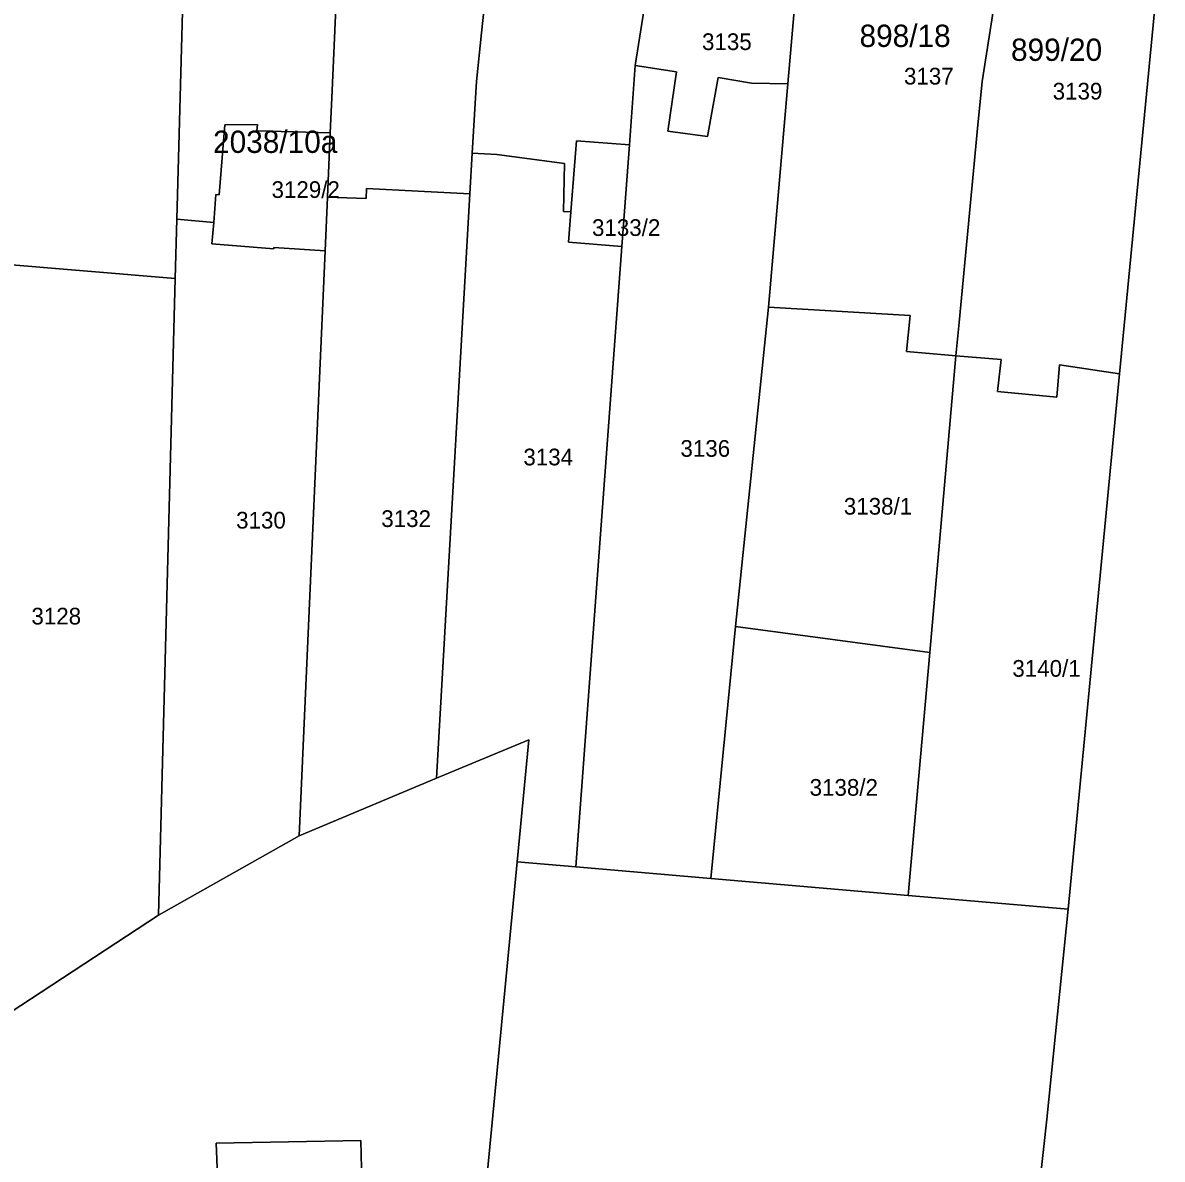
# Model space of a CAD drawing. Extents: x -570104 to -569328, y -1087857 to -1087418.
# Drawn here: x -569987.5 to -569885.2, y -1087663.8 to -1087561.8 of the extents above; entities that cross this region are included whole.
import ezdxf

# ---------------------------------------------------------------- set-up
doc = ezdxf.new("R2010")
doc.units = 0
for name, color, linetype in [('Adresní místo-text', 7, 'Continuous'), ('Parcela-polygon', 7, 'Continuous'), ('Parcela-text', 7, 'Continuous')]:
    doc.layers.add(name, color=color, linetype=linetype)

msp = doc.modelspace()

# ---------------------------------------------------------------- linework, layer by layer
at = {"layer": 'Parcela-polygon'}
for points in [[(-569997.88, -1087582.73), (-569973.85, -1087584.72), (-569973.7, -1087579.41), (-569973.18, -1087559.65), (-569972.91, -1087549.54), (-569973.1, -1087545.91), (-569997.57, -1087542.16), (-569997.86, -1087579.86)], [(-569959.94, -1087571.66), (-569959.81, -1087568.52), (-569958.91, -1087548.36), (-569973.1, -1087545.91), (-569972.91, -1087549.54), (-569973.18, -1087559.65), (-569973.7, -1087579.41), (-569970.4, -1087579.69), (-569970.2, -1087577.18), (-569969.9, -1087577.21), (-569969.4, -1087570.94), (-569966.47, -1087570.91), (-569966.53, -1087571.47)], [(-569947.4, -1087577.14), (-569947.19, -1087573.49), (-569946.82, -1087567.06), (-569946.35, -1087562.68), (-569945.39, -1087553.75), (-569944.82, -1087550.4), (-569958.91, -1087548.36), (-569959.81, -1087568.52), (-569959.94, -1087571.66), (-569960.2, -1087577.43), (-569956.73, -1087577.55), (-569956.69, -1087576.64)], [(-569932.55, -1087565.62), (-569931.05, -1087555.99), (-569930.47, -1087552.71), (-569944.82, -1087550.4), (-569945.39, -1087553.75), (-569946.35, -1087562.68), (-569946.82, -1087567.06), (-569947.19, -1087573.49), (-569944.97, -1087573.6), (-569938.9, -1087574.4), (-569939.01, -1087578.73), (-569938.34, -1087578.75), (-569937.83, -1087572.37), (-569933.08, -1087572.73)], [(-569918.85, -1087567.26), (-569917.76, -1087554.5), (-569930.47, -1087552.71), (-569931.05, -1087555.99), (-569932.55, -1087565.62), (-569928.85, -1087566.18), (-569929.63, -1087571.5), (-569926.07, -1087571.99), (-569925.11, -1087566.7), (-569922.12, -1087567.19)], [(-569899.84, -1087557.01), (-569917.76, -1087554.5), (-569918.85, -1087567.26), (-569920.58, -1087587.3), (-569907.88, -1087588.06), (-569908.19, -1087591.28), (-569904.44, -1087591.6), (-569903.76, -1087591.66), (-569903.47, -1087588.67), (-569902.54, -1087578.87), (-569901.97, -1087572.86), (-569901.85, -1087571.57), (-569901.42, -1087567.06), (-569900.4, -1087560.56)], [(-569889.08, -1087593.3), (-569885.83, -1087559.47), (-569899.84, -1087557.01), (-569900.4, -1087560.56), (-569901.42, -1087567.06), (-569901.85, -1087571.57), (-569901.97, -1087572.86), (-569902.54, -1087578.87), (-569903.47, -1087588.67), (-569903.76, -1087591.66), (-569899.7, -1087591.99), (-569900.03, -1087594.86), (-569894.72, -1087595.39), (-569894.48, -1087592.49)], [(-569933.08, -1087572.73), (-569933.75, -1087581.85), (-569937.9, -1087637.54), (-569925.77, -1087638.58), (-569923.57, -1087615.97), (-569920.58, -1087587.3), (-569918.85, -1087567.26), (-569922.12, -1087567.19), (-569925.11, -1087566.7), (-569926.07, -1087571.99), (-569929.63, -1087571.5), (-569928.85, -1087566.18), (-569932.55, -1087565.62)], [(-569959.94, -1087571.66), (-569966.53, -1087571.47), (-569966.47, -1087570.91), (-569969.4, -1087570.94), (-569969.9, -1087577.21), (-569970.2, -1087577.18), (-569970.4, -1087579.69), (-569970.56, -1087581.62), (-569965.01, -1087582.06), (-569965.01, -1087581.96), (-569960.41, -1087582.26), (-569960.2, -1087577.43)], [(-569933.08, -1087572.73), (-569937.83, -1087572.37), (-569938.34, -1087578.75), (-569938.56, -1087581.48), (-569933.75, -1087581.85)], [(-569950.39, -1087629.56), (-569942.1, -1087626.14), (-569943.15, -1087637.09), (-569937.9, -1087637.54), (-569933.75, -1087581.85), (-569938.56, -1087581.48), (-569938.34, -1087578.75), (-569939.01, -1087578.73), (-569938.9, -1087574.4), (-569944.97, -1087573.6), (-569947.19, -1087573.49), (-569947.4, -1087577.14)], [(-569962.74, -1087634.75), (-569950.39, -1087629.56), (-569947.4, -1087577.14), (-569956.69, -1087576.64), (-569956.73, -1087577.55), (-569960.2, -1087577.43), (-569960.41, -1087582.26)], [(-569973.85, -1087584.72), (-569975.37, -1087641.86), (-569962.74, -1087634.75), (-569960.41, -1087582.26), (-569965.01, -1087581.96), (-569965.01, -1087582.06), (-569970.56, -1087581.62), (-569970.4, -1087579.69), (-569973.7, -1087579.41)], [(-569997.88, -1087582.73), (-569998.44, -1087656.9), (-569998.28, -1087656.87), (-569975.37, -1087641.86), (-569973.85, -1087584.72)], [(-569923.57, -1087615.97), (-569906.12, -1087618.29), (-569903.76, -1087591.66), (-569904.44, -1087591.6), (-569908.19, -1087591.28), (-569907.88, -1087588.06), (-569920.58, -1087587.3)], [(-569894.48, -1087592.49), (-569894.72, -1087595.39), (-569900.03, -1087594.86), (-569899.7, -1087591.99), (-569903.76, -1087591.66), (-569906.12, -1087618.29), (-569908.04, -1087640.11), (-569893.7, -1087641.34), (-569889.08, -1087593.3)], [(-569906.12, -1087618.29), (-569923.57, -1087615.97), (-569925.77, -1087638.58), (-569908.04, -1087640.11)], [(-569956.87, -1087697.86), (-569957.46, -1087667.11), (-569957.07, -1087667.1), (-569957.2, -1087662.1), (-569970.17, -1087662.33), (-569969.98, -1087667.47), (-569969.48, -1087698.2)]]:
    msp.add_lwpolyline(points, close=True, dxfattribs=at)
for points in [[(-569773.93, -1087685.9), (-569793.31, -1087679.13), (-569799.7, -1087677.5), (-569818.25, -1087673.66), (-569832.64, -1087670.5), (-569838.6, -1087668.62), (-569841.57, -1087667.29), (-569832.18, -1087566.19), (-569845.77, -1087564.46), (-569885.83, -1087559.47), (-569889.08, -1087593.3), (-569893.7, -1087641.34), (-569895.61, -1087660.17), (-569904.11, -1087737.43)], [(-569950.93, -1087718.19), (-569943.15, -1087637.09), (-569942.1, -1087626.14), (-569950.39, -1087629.56), (-569962.74, -1087634.75), (-569975.37, -1087641.86), (-569998.28, -1087656.87), (-569998.44, -1087656.9), (-570032.83, -1087664.27), (-570065.08, -1087662.47), (-570091.62, -1087661.09)], [(-569904.11, -1087737.43), (-569895.61, -1087660.17), (-569893.7, -1087641.34), (-569908.04, -1087640.11), (-569925.77, -1087638.58), (-569937.9, -1087637.54), (-569943.15, -1087637.09), (-569950.93, -1087718.19)], [(-569969.98, -1087667.47), (-569970.17, -1087662.33), (-569957.2, -1087662.1), (-569957.07, -1087667.1)]]:
    msp.add_lwpolyline(points, dxfattribs=at)

# ---------------------------------------------------------------- texts
at = {"layer": 'Adresní místo-text'}
for s, p in [('898/18', (-569912.42, -1087563.95)), ('899/20', (-569898.82, -1087565.2)), ('2038/10a', (-569970.46, -1087573.46))]:
    msp.add_text(s, height=2, dxfattribs=at).set_placement(p)
at = {"layer": 'Parcela-text'}
for s, p in [('3135', (-569926.56, -1087564.23)), ('3137', (-569908.43, -1087567.32)), ('3139', (-569895.08, -1087568.67)), ('3129/2', (-569965.21, -1087577.5)), ('3133/2', (-569936.44, -1087580.91)), ('3136', (-569928.5, -1087600.73)), ('3134', (-569942.6, -1087601.5)), ('3138/1', (-569913.83, -1087605.92)), ('3132', (-569955.36, -1087607.03)), ('3130', (-569968.39, -1087607.17)), ('3128', (-569986.77, -1087615.78)), ('3140/1', (-569898.7, -1087620.47)), ('3138/2', (-569916.9, -1087631.15))]:
    msp.add_text(s, height=1.5, dxfattribs=at).set_placement(p)

doc.saveas('drawing.dxf')
